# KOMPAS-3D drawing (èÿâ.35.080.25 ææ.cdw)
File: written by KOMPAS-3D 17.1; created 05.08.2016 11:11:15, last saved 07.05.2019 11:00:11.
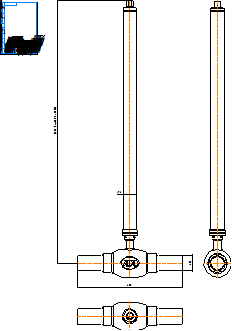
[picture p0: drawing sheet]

Sheet 1: A4, portrait

Title block, sheet 1: name: КШГ.35.080.25 СС; material: Внимание! Данный продукт является объектом авторского права ООО «Торговый Дом АДЛ». / Запрещается изменение, копирование, распространение / (в том числе путем копирования на другие сайты и ресурсы в Интернете) / или любое иное использование информации и объектов без предварительного / согласия правообладателя (ООО «Торговый Дом АДЛ»).; sheets: 1; organisation: ООО "Торговый дом АДЛ"; sheet format: A4; stored path: C:\Users\kka\KOMPAS_Work\Модели кранов для исследований\DN100\С удлинением\КШГ.35.080.25 СС _ Шаровой кран БИВАЛ Ду80 Ру2,5 МПа полнопроходной под приварку, c удлинением штока H=650 Lстр600.cdw; drawn by: Климкович К.А.; drawn by, date: 07.12.16

Views: Вид 1, Проекционный вид 2
Referenced files in C:\Users\kka\KOMPAS_Work\Модели кранов для исследований\DN100\С удлинением\: КШГ.35.080.25 СС Lстр600.a3d, КШГ.35.080.25 СС Lстр600.a3d!Деталь (локальная).m3d
Referenced files in C:\Users\kka\KOMPAS_Work\Модели кранов для исследований\DN100\: АПТА.0203-1180.03.01-11 _ Патрубок сварной Ду80ПП.m3d
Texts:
  Klimkovich
  ADL
  (от 380 до 5000)
Dimensions and other numbers on the sheet: 1500; 600; 89; 76; 1:1; 1; 07.12.16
